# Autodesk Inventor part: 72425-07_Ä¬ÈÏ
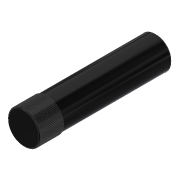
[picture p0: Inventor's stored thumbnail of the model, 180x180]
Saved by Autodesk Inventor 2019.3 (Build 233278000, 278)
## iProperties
Created: 2010-06
Part Number: 72425-07_Ä¬ÈÏ
Material: Ogólny
Document SubType Name: Modeling
Designer: CADENGINEERING4
Density: 1 g/cm^3
Appearance: Gładki — czarny
Author: CADENGINEERING4
Revision Number: ÈÎºÎ
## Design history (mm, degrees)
feature "NONE"
node "Bryła1"
